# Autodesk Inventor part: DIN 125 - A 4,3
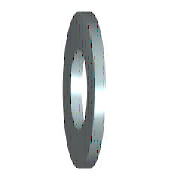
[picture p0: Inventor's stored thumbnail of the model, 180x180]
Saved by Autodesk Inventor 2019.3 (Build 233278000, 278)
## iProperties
Created: 2018-01
Part Number: DIN 125 - A 4,3
Material: Ocel, měkká
Description: Podložka
Document SubType Name: Modeling
Standard: DIN 125
Designer: B-hon
Standards Organization: DIN
Language: cs-CZ
Size Designation: A 4,3
Categories: <MemberInstance><Categories><Category DisplayName="Spojovací materiál" InternalName="e4da775c-781d-43d5-af7c-5136215cf5a6" Mnemonic="FSTN"><Category DisplayName
Density: 7.85 g/cm^3
Appearance: Pololeštěná
IsCustomPart: 0
Author: B-hon
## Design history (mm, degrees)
sketch "Náčrt"
  geometry: C1 r 4.5 at (0, 0); C2 r 2.15 at (0, 0); 1 further point
  constraints: 2 centre point, 2 coincident
  dimensions: "d0" = 4.3 diameter of C2 (= SD1); "d1" = 9 diameter of C1 (= SD2)
extrude "Těleso" new body sketch "Náčrt" distance "d2" = 0.8 (= SD); taper "d3" = 0 deg
workaxis "Work Axis1"
workplane "Work Plane1"
body "Solid1"
other parameters: "SD1" = 4.3 [user parameter; used in 1 equation term], "SD2" = 9 [user parameter; used in 1 equation term], "SD" = 0.8 [user parameter; used in 1 equation term], "d4" = 0, "d5" = 0, "d6" = 0, "d7" = 0, "NND" = 4 [user parameter]
